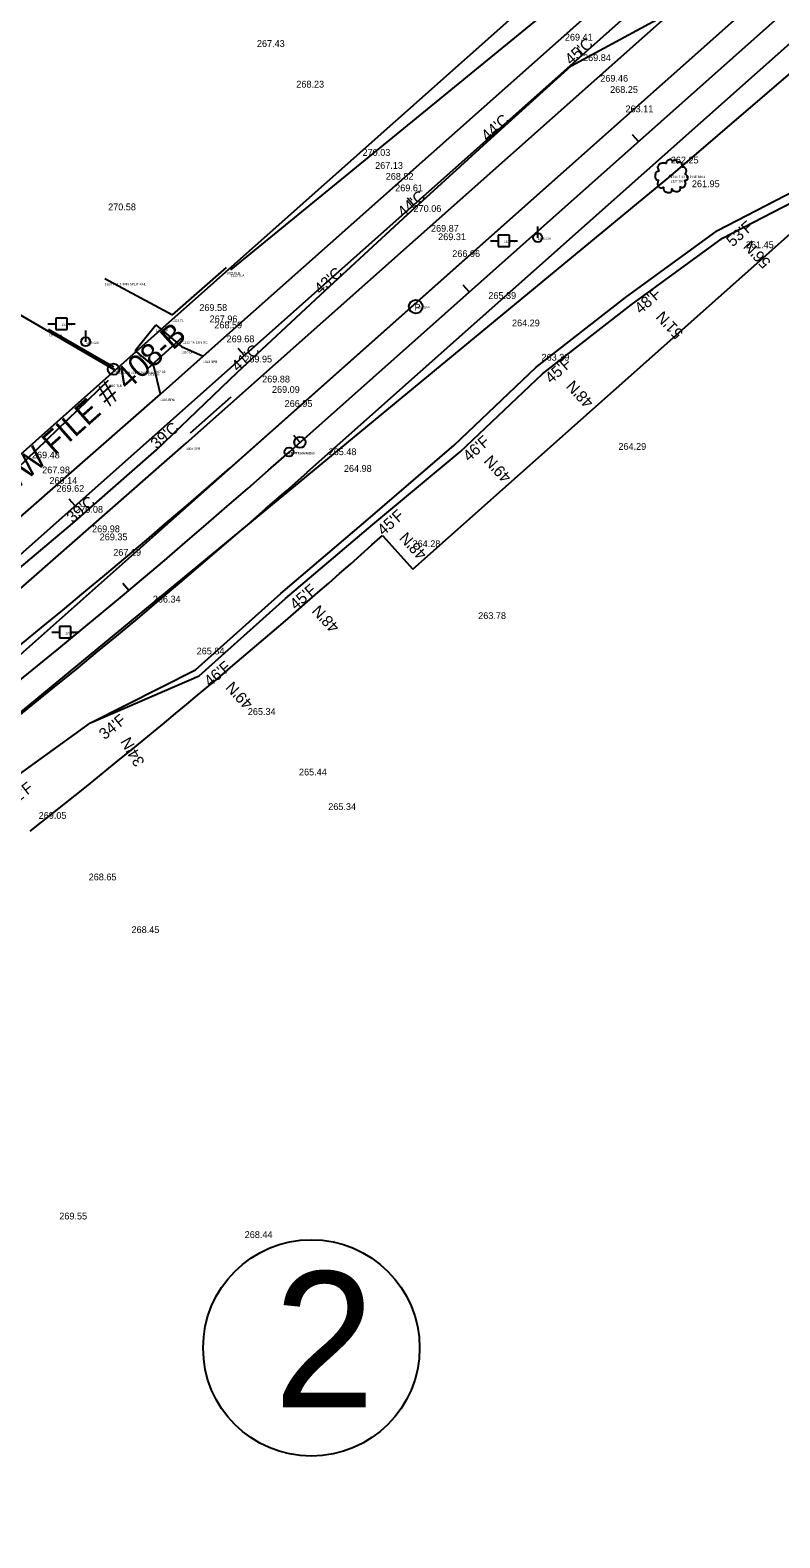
# Model space of a CAD drawing. Extents: x 49683 to 58852, y 49525 to 54803.
# Drawn here: x 52600 to 52931, y 50294 to 50960 of the extents above; entities that cross this region are included whole.
import ezdxf

# ---------------------------------------------------------------- set-up
doc = ezdxf.new("R2010")
doc.units = 0
for name, color, linetype in [('Level 1', 7, 'Continuous'), ('Level 11', 7, 'Continuous'), ('Level 12', 7, 'Continuous'), ('Level 13', 7, 'Continuous'), ('Level 18', 7, 'Continuous'), ('Level 19', 7, 'Continuous'), ('Level 20', 7, 'Continuous'), ('Level 25', 7, 'Continuous'), ('Level 3', 7, 'Continuous'), ('Level 32', 7, 'Continuous'), ('Level 33', 7, 'Continuous'), ('Level 34', 7, 'Continuous'), ('Level 48', 7, 'Continuous'), ('Level 51', 7, 'Continuous'), ('Level 53', 7, 'Continuous'), ('Level 56', 7, 'Continuous'), ('Level 58', 7, 'Continuous'), ('Level 59', 7, 'Continuous'), ('Level 6', 7, 'Continuous'), ('Level 61', 7, 'Continuous'), ('Level 62', 7, 'Continuous'), ('Level 8', 7, 'Continuous'), ('Level 9', 7, 'Continuous')]:
    doc.layers.add(name, color=color, linetype=linetype)

# ---------------------------------------------------------------- blocks, each defined once
blk = doc.blocks.new('PP')
at = {"layer": 'Level 9'}
for p, q in [((2.53, 2.45), (-2.47, 2.45)), ((-2.47, 2.45), (-2.47, -2.55)), ((2.53, -2.55), (2.53, 2.45)), ((-5.91, -0.11), (-2.44, -0.11)), ((-2.47, -2.55), (2.53, -2.55)), ((2.45, -0.11), (6.09, -0.11))]:
    blk.add_line(p, q, dxfattribs=at)
blk = doc.blocks.new('GW')
at = {"layer": 'Level 9'}
blk.add_line((0, 0), (0, 5), dxfattribs=at)
blk.add_circle((0, 0), 2, dxfattribs=at)
blk = doc.blocks.new('TPP')
at = {"layer": 'Level 9'}
blk.add_circle((0, 0), 3, dxfattribs=at)
blk.add_text('P', height=3, dxfattribs=at).set_placement((-0.59, -1.73))
blk = doc.blocks.new('T1')
at = {"layer": 'Level 11'}
for centre, radius in [((0, 0), 0.25), ((-0.01, -0.02), 0.0001)]:
    blk.add_circle(centre, radius, dxfattribs=at)
for points in [[(0.13, 7.17), (-0.17, 7.19), (-0.49, 7.09), (-0.74, 6.99), (-0.97, 6.92), (-1.19, 6.82), (-1.49, 6.64), (-1.72, 6.44), (-1.84, 6.19), (-1.89, 5.97), (-1.94, 5.69), (-1.94, 5.52), (-2.07, 5.49), (-2.22, 5.52), (-2.47, 5.59), (-2.72, 5.59), (-2.97, 5.59), (-3.32, 5.57), (-3.67, 5.57), (-3.94, 5.52), (-4.27, 5.47), (-4.64, 5.34), (-4.99, 5.22), (-5.29, 4.97), (-5.54, 4.49), (-5.67, 4.14), (-5.82, 3.89), (-5.67, 3.44), (-5.49, 3.09), (-5.47, 2.89), (-5.39, 2.47), (-5.29, 2.24), (-5.17, 2.04), (-5.24, 2.02), (-5.62, 1.97), (-5.92, 1.87), (-6.34, 1.64), (-6.57, 1.42), (-6.67, 1.09), (-6.69, 0.75), (-6.79, 0.55), (-6.87, 0.27), (-6.89, 0.2), (-6.94, -0.13), (-6.84, -0.58), (-6.82, -0.93), (-6.69, -1.15), (-6.54, -1.33), (-6.37, -1.58), (-5.97, -1.8), (-5.64, -1.9), (-5.44, -1.93), (-5.62, -2.43), (-5.67, -2.78), (-5.79, -3.18), (-5.79, -3.25), (-5.84, -3.73), (-5.69, -4.05), (-5.62, -4.43), (-5.44, -4.65), (-5.17, -4.95), (-4.84, -5.18), (-4.34, -5.3), (-3.94, -5.28), (-3.37, -5.1), (-3.12, -5.03), (-3.14, -5.2), (-3.12, -5.58), (-3.12, -6), (-2.97, -6.33), (-2.87, -6.6), (-2.72, -6.85), (-2.39, -7.08), (-1.99, -7.15), (-1.57, -7.3), (-1.12, -7.38), (-0.62, -7.4), (-0.02, -7.25), (0.26, -7.13), (0.36, -6.95), (0.56, -6.58), (0.51, -6.35), (0.53, -5.75), (0.63, -5.93), (0.81, -6.28), (1.31, -6.58), (1.71, -6.75), (2.18, -6.9), (2.48, -6.98), (2.96, -6.9), (3.33, -6.83), (3.71, -6.7), (4.01, -6.43), (4.18, -6.15), (4.23, -5.88), (4.31, -5.5), (4.36, -5.33)], [(4.36, -5.33), (4.28, -5.15), (4.23, -4.9), (4.31, -4.93), (4.48, -4.98), (4.75, -5.1), (4.98, -5.18), (5.3, -5.15), (5.58, -5.05), (6.03, -4.78), (6.3, -4.3), (6.58, -3.9), (6.65, -3.58), (6.6, -3.35), (6.58, -2.85), (6.38, -2.6), (6.33, -2.48), (6.23, -2.08), (6.3, -2.03), (6.58, -1.98), (6.95, -1.85), (7.23, -1.73), (7.45, -1.55), (7.53, -1.33), (7.5, -0.93), (7.55, -0.53), (7.48, -0.38), (7.38, -0.23), (7.3, -0.03), (7.15, 0.12), (7.05, 0.27), (6.95, 0.37), (6.83, 0.52), (6.65, 0.65), (6.5, 0.7), (6.45, 0.85), (6.6, 1.04), (6.65, 1.14), (6.68, 1.37), (6.9, 1.72), (6.95, 2.12), (6.9, 2.54), (6.85, 2.82), (6.7, 3.09), (6.5, 3.34), (6.38, 3.52), (6.2, 3.64), (5.88, 3.77), (5.63, 3.82), (5.28, 3.82), (5.08, 3.87), (5.1, 3.92), (5.1, 4.07), (5.1, 4.34), (5.03, 4.79), (4.88, 5.29), (4.88, 5.32), (4.78, 5.57), (4.56, 5.77), (4.38, 5.87), (4.18, 5.99), (3.93, 6.02), (3.63, 6.02), (3.36, 5.97), (3.16, 5.87), (2.98, 5.74), (2.91, 5.89), (2.81, 6.19), (2.76, 6.34), (2.61, 6.52), (2.38, 6.72), (1.93, 6.84), (1.31, 6.77), (1.01, 6.57), (0.86, 6.39), (0.81, 6.52), (0.61, 6.72), (0.51, 6.89), (0.33, 7.02), (0.18, 7.12), (0.08, 7.17)]]:
    blk.add_spline(points, degree=3, dxfattribs=at)
blk = doc.blocks.new('IP')
at = {"layer": 'Level 12'}
for radius in [2.5, 0.25]:
    blk.add_circle((0, 0), radius, dxfattribs=at)

msp = doc.modelspace()

# ---------------------------------------------------------------- linework, layer by layer
at = {"layer": 'Level 1'}
for p, q in [((52544.81, 50683.3), (55534.58, 53340.86)), ((52843.9, 50949.16), (52841.24, 50952.15)), ((52769.16, 50882.73), (52766.5, 50885.72)), ((52694.42, 50816.29), (52691.76, 50819.28)), ((52619.68, 50749.85), (52617.02, 50752.84))]:
    msp.add_line(p, q, dxfattribs=at)
at = {"layer": 'Level 11'}
for p, q in [((52882.73, 50895.61), (53245.86, 51207.55)), ((52688.43, 50854.08), (52940.3, 51059.99)), ((52579.25, 50645.17), (52882.73, 50895.61)), ((52527.71, 50702.05), (52634.35, 50805.36))]:
    msp.add_line(p, q, dxfattribs=at)
at = {"layer": 'Level 12'}
msp.add_line((52386.57, 50955.87), (52637.37, 50809.73), dxfattribs=at)
at = {"layer": 'Level 13'}
for p, q in [((52637.37, 50809.73), (53363.85, 51455.49)), ((53407.7, 51406.16), (52566.74, 50658.64)), ((52563.41, 50743.99), (52637.37, 50809.73))]:
    msp.add_line(p, q, dxfattribs=at)
at = {"layer": 'Level 18'}
for p, q in [((52838.7, 50944.25), (52884, 50968.55)), ((52801.74, 50910.57), (52838.7, 50944.25)), ((52764.78, 50876.89), (52801.74, 50910.57)), ((52903.42, 50871.43), (52949.21, 50895.18)), ((52905.54, 50868.02), (52952.04, 50892.14)), ((52728.03, 50842.97), (52764.78, 50876.89)), ((52862.84, 50841.82), (52903.42, 50871.43)), ((52865.2, 50838.59), (52905.54, 50868.02)), ((52691.47, 50808.84), (52728.03, 50842.97)), ((52823.29, 50811.06), (52862.84, 50841.82)), ((52826.05, 50808.16), (52865.2, 50838.59)), ((52655.68, 50774.63), (52691.47, 50808.84)), ((52787.03, 50776.59), (52823.29, 50811.06)), ((52789.79, 50773.69), (52826.05, 50808.16)), ((52618.52, 50742.07), (52655.68, 50774.63)), ((52749.18, 50743.91), (52787.03, 50776.59)), ((52751.13, 50741.63), (52789.79, 50773.69)), ((52580.75, 50710.21), (52618.52, 50742.07)), ((52710.59, 50711.18), (52749.18, 50743.91)), ((52712.56, 50708.92), (52751.13, 50741.63)), ((52672.8, 50677.37), (52710.59, 50711.18)), ((52674.45, 50674.82), (52712.56, 50708.92)), ((52626.4, 50654.08), (52672.8, 50677.37)), ((52626.4, 50654.08), (52674.45, 50674.82)), ((52585.47, 50624.39), (52626.4, 50654.08))]:
    msp.add_line(p, q, dxfattribs=at)
at = {"layer": 'Level 19'}
for p, q in [((52714.15, 50773.62), (54181.77, 52078.16)), ((52868.45, 50910.77), (52865.79, 50913.76)), ((52793.71, 50844.34), (52791.05, 50847.33)), ((52718.97, 50777.9), (52716.31, 50780.89)), ((52643.35, 50712.47), (52640.78, 50715.54))]:
    msp.add_line(p, q, dxfattribs=at)
for centre, radius in [((52718.97, 50777.9), 2.5), ((52714.15, 50773.62), 2)]:
    msp.add_circle(centre, radius, dxfattribs=at)
msp.add_arc((50539, 53220.69), 3274.06, 284.51284, 311.63337, dxfattribs=at)
at = {"layer": 'Level 20'}
for p, q in [((52706.17, 50782.58), (53452.43, 51445.92)), ((52722.12, 50764.65), (53468.37, 51427.98))]:
    msp.add_line(p, q, dxfattribs=at)
for radius in [3262.06, 3286.06]:
    msp.add_arc((50539, 53220.69), radius, 284.51246, 311.63318, dxfattribs=at)
at = {"layer": 'Level 25'}
msp.add_circle((52724.02, 50377.96), 47.8, dxfattribs=at)
at = {"layer": 'Level 3'}
for p, q in [((52676.2, 50815.96), (52945.93, 51055.32)), ((52668.7, 50777.53), (52961.4, 51037.52)), ((52657.35, 50799.14), (52676.2, 50815.96)), ((52536.19, 50693.05), (52657.35, 50799.14)), ((52552.71, 50675.77), (52668.7, 50777.53))]:
    msp.add_line(p, q, dxfattribs=at)
at = {"layer": 'Level 33'}
for p, q in [((52768.8, 50721.85), (53814.15, 51651.04)), ((52755.51, 50736.8), (52768.8, 50721.85))]:
    msp.add_line(p, q, dxfattribs=at)
msp.add_arc((50539, 53220.69), 3329.06, 308.24612, 311.74424, dxfattribs=at)
at = {"layer": 'Level 34'}
msp.add_line((52670.64, 50782.13), (52688.59, 50798.06), dxfattribs=at)
at = {"layer": 'Level 6'}
msp.add_line((52667.22, 50824.46), (52651.63, 50810.3), dxfattribs=at)
at = {"layer": 'Level 8'}
for p, q in [((52662.65, 50834.17), (52686.48, 50855.13)), ((52632.81, 50850.29), (52662.65, 50834.17)), ((52636.74, 50811.07), (52607.92, 50827.67)), ((52646.27, 50818.43), (52655.35, 50829.84)), ((52655.35, 50829.84), (52666.62, 50820.18)), ((52666.62, 50820.18), (52676.2, 50815.96)), ((52654.44, 50811.48), (52646.27, 50818.43)), ((52657.35, 50799.14), (52654.44, 50811.48))]:
    msp.add_line(p, q, dxfattribs=at)

# ---------------------------------------------------------------- block references
at = {"layer": 'Level 11'}
msp.add_blockref('T1', (52882.73, 50895.61), dxfattribs=at)
at = {"layer": 'Level 12'}
msp.add_blockref('IP', (52636.62, 50810.17), dxfattribs=at)
at = {"layer": 'Level 9'}
for name, p in [('GW', (52824.02, 50868.26)), ('PP', (52809, 50866.96)), ('TPP', (52770.13, 50837.82)), ('PP', (52613.57, 50830.29)), ('GW', (52624.36, 50822.3)), ('PP', (52615.32, 50694.1))]:
    msp.add_blockref(name, p, dxfattribs=at)

# ---------------------------------------------------------------- texts
at = {"layer": 'Level 25'}
msp.add_text("33' R/W FILE # 408-B", height=10, rotation=41.63333, dxfattribs=at).set_placement((52572.62, 50738.12))
msp.add_text('2', height=60, dxfattribs=at).set_placement((52707.42, 50351.68))
at = {"layer": 'Level 32'}
for s, p in [('267.43', (52699.98, 50952.52)), ('269.41', (52836, 50955.33)), ('269.84', (52844.03, 50946.28)), ('269.46', (52851.64, 50937.16)), ('268.23', (52717.38, 50934.57)), ('268.25', (52855.98, 50932.23)), ('263.11', (52862.77, 50923.68)), ('270.03', (52746.62, 50904.42)), ('267.13', (52752.19, 50898.68)), ('262.25', (52882.8, 50901.07)), ('268.82', (52756.87, 50893.86)), ('261.95', (52892.09, 50890.59)), ('269.61', (52761.05, 50888.76)), ('270.58', (52634.26, 50880.38)), ('270.06', (52769.16, 50879.66)), ('269.87', (52776.86, 50870.91)), ('269.31', (52780.03, 50867.2)), ('261.45', (52915.96, 50863.65)), ('266.96', (52786.26, 50859.74)), ('269.58', (52674.56, 50835.92)), ('265.39', (52802.19, 50841.24)), ('267.96', (52679.1, 50830.92)), ('264.29', (52812.64, 50829.12)), ('268.59', (52681.16, 50828.21)), ('269.68', (52686.58, 50822.08)), ('269.95', (52694.4, 50813.18)), ('263.39', (52825.69, 50813.97)), ('269.88', (52702.29, 50804.34)), ('269.09', (52706.63, 50799.75)), ('266.95', (52712.21, 50793.54)), ('269.48', (52600.61, 50770.8)), ('265.48', (52731.65, 50772.24)), ('264.29', (52859.63, 50774.58)), ('267.98', (52605.13, 50764.2)), ('264.98', (52738.39, 50764.86)), ('269.14', (52608.33, 50759.52)), ('269.62', (52611.44, 50756.05)), ('270.08', (52619.73, 50746.79)), ('269.98', (52627.18, 50738.19)), ('269.35', (52630.53, 50734.64)), ('264.28', (52768.72, 50731.62)), ('267.19', (52636.52, 50727.8)), ('266.34', (52653.99, 50707.13)), ('263.78', (52797.71, 50699.86)), ('265.84', (52673.36, 50684.23)), ('265.34', (52695.96, 50657.5)), ('265.44', (52718.56, 50630.78)), ('269.05', (52603.58, 50611.6)), ('265.34', (52731.48, 50615.51)), ('268.65', (52625.67, 50584.45)), ('268.45', (52644.6, 50561.18)), ('269.55', (52612.69, 50434.68)), ('268.44', (52694.58, 50426.49))]:
    msp.add_text(s, height=3, dxfattribs=at).set_placement(p)
at = {"layer": 'Level 48'}
for s, rotation, p in [("45'C", 41.63336, (52838.7, 50944.25)), ("44'C", 41.63339, (52801.74, 50910.57)), ("44'C", 41.63339, (52764.78, 50876.89)), ("53'F", 41.63339, (52910.07, 50863.96)), ("56'N", 132.85283, (52927.27, 50857.56)), ("43'C", 41.63336, (52728.03, 50842.97)), ("48'F", 41.63336, (52869.49, 50834.35)), ("51'N", 132.85283, (52888.64, 50826.37)), ("41'C", 41.63336, (52691.47, 50808.84)), ("45'F", 41.63332, (52829.93, 50803.59)), ("48'N", 132.85283, (52849.04, 50795.8)), ("39'C", 40.8711, (52655.68, 50774.63)), ("46'F", 41.63336, (52793.68, 50769.12)), ("49'N", 132.85283, (52812.72, 50762.8)), ("39'C", 39.99614, (52618.52, 50742.07)), ("45'F", 41.63339, (52755.83, 50736.44)), ("48'N", 132.85283, (52775.37, 50728.77)), ("45'F", 40.8711, (52717.13, 50703.62)), ("48'N", 132.85283, (52736.73, 50696.55)), ("46'F", 39.99611, (52679.23, 50669.71)), ("49'N", 132.85283, (52698.61, 50662.78)), ("34'F", 39.1211, (52632.71, 50646.32)), ("34'N", 119.91701, (52650.58, 50636.55)), ("32'F", 38.24614, (52591.66, 50616.54))]:
    msp.add_text(s, height=5, rotation=rotation, dxfattribs=at).set_placement(p)
at = {"layer": 'Level 51'}
for s in ['24 PT 506+93.55', '180 PT 506+93.55 ']:
    msp.add_text(s, height=1, dxfattribs=at).set_placement((52714.15, 50772.62))
at = {"layer": 'Level 53'}
for s, p in [('1312 EPL', (52676.2, 50812.96)), ('1305 EPL', (52657.35, 50796.14)), ('1304 EPR', (52668.7, 50774.53))]:
    msp.add_text(s, height=1, dxfattribs=at).set_placement(p)
at = {"layer": 'Level 56'}
for s, p in [('1313 PA 18IN RC', (52667.22, 50821.46)), ('1314 PB', (52651.63, 50807.3))]:
    msp.add_text(s, height=1, dxfattribs=at).set_placement(p)
at = {"layer": 'Level 58'}
for s, p in [('1322 FLB', (52686.48, 50852.13)), ('1320 FLA B 40IN SPLIT RAIL', (52632.81, 50847.29)), ('1321 FL', (52662.65, 50831.17)), ('1317 FLB', (52607.92, 50824.67)), ('1309 DP', (52655.35, 50826.84)), ('1308 DP', (52646.27, 50815.43)), ('1310 DP', (52666.62, 50817.18)), ('1311 DPB', (52676.2, 50812.96)), ('1316 FLA B 40IN SPLIT RAIL', (52636.74, 50808.07)), ('1307 DP', (52654.44, 50808.48)), ('1306 DPA', (52657.35, 50796.14))]:
    msp.add_text(s, height=1, dxfattribs=at).set_placement(p)
at = {"layer": 'Level 59'}
for s, p in [('1325 PP', (52809, 50865.96)), ('1326 GW', (52824.02, 50867.26)), ('1324 TPP', (52770.13, 50836.82)), ('1319 PP', (52613.57, 50829.29)), ('1318 GW', (52624.36, 50821.3)), ('1303 PP', (52615.32, 50693.1))]:
    msp.add_text(s, height=1, dxfattribs=at).set_placement(p)
at = {"layer": 'Level 61'}
for s, p in [('1710 T 10 IN PINE BM 4', (52882.73, 50894.61)), ('1327 TR', (52882.73, 50892.62)), ('1323 TLA', (52688.43, 50851.08)), ('1315 TLB', (52634.35, 50802.36))]:
    msp.add_text(s, height=1, dxfattribs=at).set_placement(p)
at = {"layer": 'Level 62'}
msp.add_text('1008 IP', height=1, dxfattribs=at).set_placement((52636.62, 50809.17))

doc.saveas('drawing.dxf')
